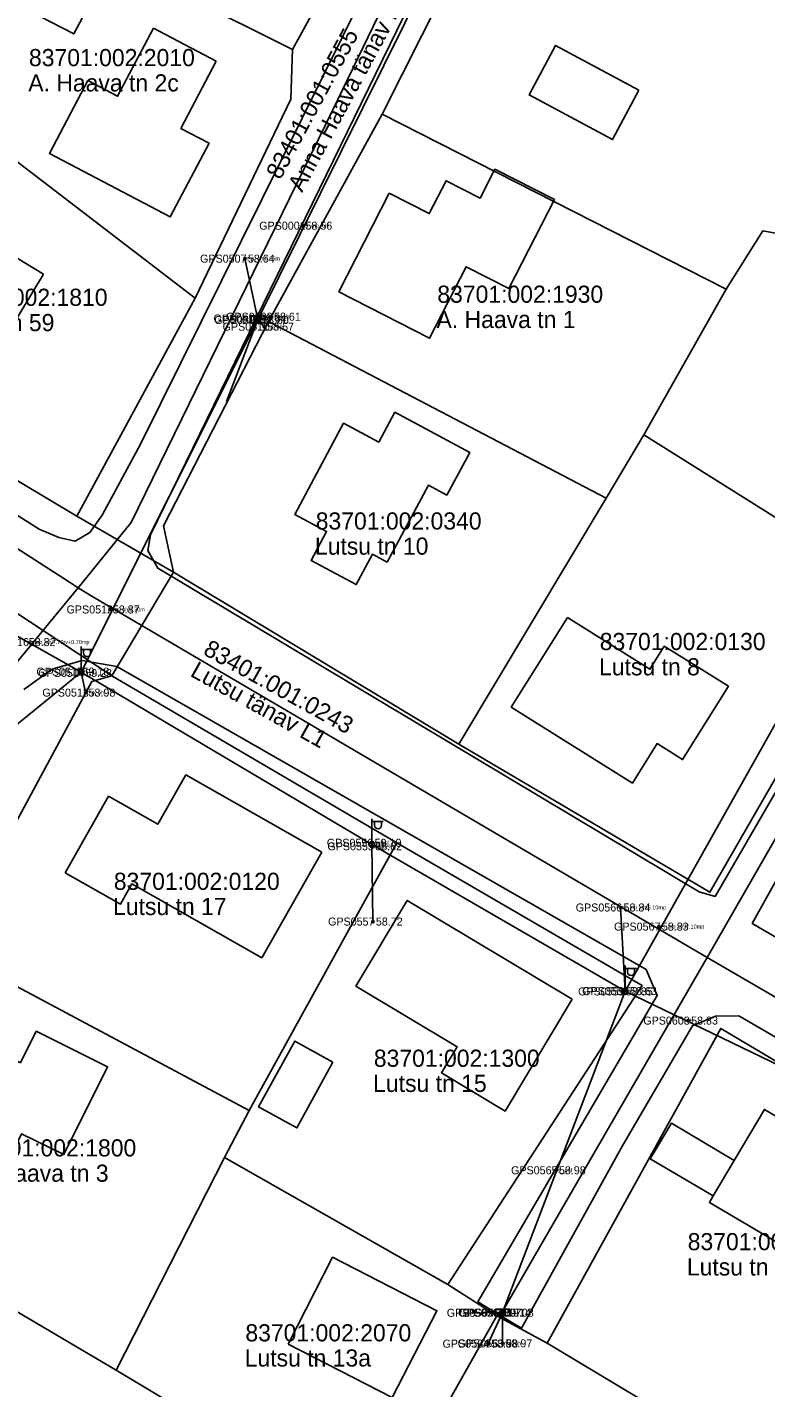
# Model space of a CAD drawing. Extents: x 580119 to 583377, y 6518915 to 6520820.
# Drawn here: x 581946.3 to 582010.9, y 6520218 to 6520337 of the extents above; entities that cross this region are included whole.
import ezdxf

# ---------------------------------------------------------------- set-up
doc = ezdxf.new("R2010")
doc.units = 0
for name, color, linetype in [('ELRAJATISMP', 7, 'Continuous'), ('Hoone Elu- või ühiskondlik hoone', 7, 'Continuous'), ('Hoone Kõrval- või tootmishoone', 7, 'Continuous'), ('L_AADRESS', 7, 'Continuous'), ('MAAMUDEL', 7, 'Continuous'), ('MOOTKORG-EH2000', 7, 'Continuous'), ('MOOTMPUNKT', 7, 'Continuous'), ('MOOTNR', 7, 'Continuous'), ('MPOHULIIN', 7, 'Continuous'), ('PIIR', 7, 'Continuous'), ('POST', 7, 'Continuous'), ('Rippe kõrgus', 7, 'Continuous'), ('SIOHULIIN', 7, 'Continuous'), ('Tee Liiklusala', 7, 'Continuous'), ('Tee Tänav Kruuskate', 7, 'Continuous'), ('Tee Tänav Püsikate', 7, 'Continuous'), ('TUNNUS', 7, 'Continuous')]:
    doc.layers.add(name, color=color, linetype=linetype)

msp = doc.modelspace()

# ---------------------------------------------------------------- linework, layer by layer
at = {"layer": 'ELRAJATISMP'}
for p, q in [((581966.36, 6520311.73), (581966.36, 6520311.13)), ((581966.63, 6520311.73), (581966.63, 6520311.13)), ((581987.76, 6520224.87), (581987.76, 6520224.28)), ((581988.03, 6520224.87), (581988.03, 6520224.28))]:
    msp.add_line(p, q, dxfattribs=at)
for points in [[(581965.9, 6520311.73), (581967.1, 6520311.73), (581967.1, 6520311.13), (581965.9, 6520311.13)], [(581987.3, 6520224.87), (581988.49, 6520224.87), (581988.49, 6520224.28), (581987.3, 6520224.28)]]:
    msp.add_lwpolyline(points, close=True, dxfattribs=at)
at = {"layer": 'Hoone Elu- või ühiskondlik hoone'}
for points in [[(581962.85, 6520334.01), (581959.76, 6520328.13), (581962.23, 6520326.83), (581958.83, 6520320.38), (581948.27, 6520325.94), (581951.63, 6520332.31), (581954.23, 6520330.94), (581957.38, 6520336.89)], [(581977.97, 6520322.47), (581981.48, 6520320.68), (581982.95, 6520323.55), (581985.92, 6520322.03), (581987.22, 6520324.56), (581992.42, 6520321.9), (581988.43, 6520314.12), (581984.7, 6520316.02), (581981.51, 6520309.78), (581973.56, 6520313.84)], [(581947.76, 6520315.39), (581943.15, 6520307.8), (581929.97, 6520315.78), (581934.59, 6520323.38)], [(581978.46, 6520303.3), (581985.01, 6520299.79), (581983.01, 6520296.06), (581981.4, 6520296.93), (581977.79, 6520290.2), (581976.51, 6520290.89), (581975.09, 6520288.23), (581971.15, 6520290.35), (581972.5, 6520292.87), (581969.72, 6520294.36), (581973.99, 6520302.34), (581977.06, 6520300.69)], [(581993.55, 6520285.36), (582000.76, 6520280.84), (582002.02, 6520282.85), (582007.63, 6520279.34), (582003.62, 6520272.93), (582001.39, 6520274.33), (581999.23, 6520270.88), (581988.64, 6520277.52)], [(581949.64, 6520263.03), (581953.44, 6520269.73), (581957.74, 6520267.28), (581960.19, 6520271.59), (581972.08, 6520264.83), (581966.83, 6520255.6), (581955.47, 6520262.06), (581954.47, 6520260.29)], [(581993.96, 6520251.97), (581988.1, 6520242.2), (581982.56, 6520245.53), (581983.93, 6520247.81), (581975.06, 6520253.13), (581979.55, 6520260.62)], [(581939.93, 6520249.3), (581945.73, 6520246.42), (581947.11, 6520249.18), (581953.35, 6520246.07), (581949.53, 6520238.4), (581945.84, 6520240.22), (581941.75, 6520232), (581933.39, 6520236.16)], [(582022.14, 6520235.63), (582017.33, 6520227.49), (582005.97, 6520234.21), (582006.31, 6520234.79), (582008.14, 6520237.89), (582010.77, 6520242.34)], [(581969.13, 6520221.82), (581973.03, 6520229.42), (581982.14, 6520224.74), (581978.24, 6520217.15)]]:
    msp.add_lwpolyline(points, close=True, dxfattribs=at)
at = {"layer": 'Hoone Kõrval- või tootmishoone'}
for points in [[(581952.19, 6520339.77), (581950.4, 6520336.39), (581944.53, 6520339.46), (581946.33, 6520342.85)], [(581999.81, 6520331.46), (581997.5, 6520327.15), (581990.2, 6520331.05), (581992.51, 6520335.37)], [(581973.06, 6520246.48), (581969.91, 6520240.72), (581966.55, 6520242.56), (581969.71, 6520248.32)], [(582008.14, 6520237.89), (582006.31, 6520234.79), (582000.8, 6520238.03), (582002.64, 6520241.14)]]:
    msp.add_lwpolyline(points, close=True, dxfattribs=at)
at = {"layer": 'MOOTMPUNKT'}
for centre in [(581970.39, 6520319.62), (581965.36, 6520316.74), (581966.39, 6520311.5), (581966.6, 6520311.37), (581967.05, 6520310.79), (581967.64, 6520311.66), (581953.55, 6520286.06), (581950.91, 6520280.62), (581951.14, 6520280.51), (581951.43, 6520278.79), (581976.44, 6520265.66), (581976.49, 6520265.35), (581998.2, 6520260), (581976.55, 6520258.77), (582001.55, 6520258.33), (581998.41, 6520252.66), (581998.77, 6520252.69), (582004.11, 6520250.11), (581992.55, 6520237.02), (581986.93, 6520224.56), (581987.77, 6520224.57), (581988.01, 6520224.57), (581986.63, 6520221.86), (581987.88, 6520221.89)]:
    msp.add_circle(centre, 0.1, dxfattribs=at)
at = {"layer": 'MPOHULIIN'}
for p, q in [((581966.5, 6520311.43), (581965.36, 6520316.74)), ((581966.5, 6520311.43), (581967.64, 6520311.66)), ((581966.5, 6520311.43), (581967.05, 6520310.79)), ((581998.59, 6520252.67), (582017.03, 6520285.52)), ((581951.03, 6520280.57), (581951.43, 6520278.79)), ((581976.46, 6520265.51), (581976.55, 6520258.77)), ((581998.59, 6520252.67), (581998.2, 6520260)), ((581987.89, 6520224.57), (581998.59, 6520252.67)), ((581987.89, 6520224.57), (581985.24, 6520224.54)), ((581987.89, 6520224.57), (581987.88, 6520221.89))]:
    msp.add_line(p, q, dxfattribs=at)
for points in [[(581951.03, 6520280.57), (581966.5, 6520311.43), (581981.19, 6520341.05)], [(581951.03, 6520280.57), (581930.23, 6520292.3), (581906.16, 6520306.38), (581867.76, 6520298.22)], [(581951.03, 6520280.57), (581930.01, 6520263.47), (581928.35, 6520263.55)], [(581998.59, 6520252.67), (581976.46, 6520265.51), (581951.03, 6520280.57)], [(582047.56, 6520226.26), (582023.23, 6520240.78), (581998.59, 6520252.67)]]:
    msp.add_lwpolyline(points, dxfattribs=at)
at = {"layer": 'PIIR'}
for points in [[(581957.49, 6520399.79), (581993.27, 6520378.24), (581969.51, 6520335.03), (581932.94, 6520353.26)], [(581993.27, 6520378.24), (581999.92, 6520374.14), (581977.35, 6520329.37), (581967.43, 6520311.25), (581958.23, 6520293.37), (581959.11, 6520289.32), (581950.66, 6520294.21), (581961, 6520313.29), (581969.36, 6520330.69), (581969.51, 6520335.03)], [(581999.92, 6520374.14), (582031.69, 6520354.73), (582013.33, 6520318.68), (582010.64, 6520319.17), (582007.43, 6520314.06), (581977.35, 6520329.37)], [(581921.06, 6520341.05), (581927.81, 6520351.97), (581931.31, 6520350.19), (581932.94, 6520353.26), (581969.51, 6520335.03), (581969.36, 6520330.69), (581961, 6520313.29), (581938.63, 6520330.42)], [(581938.63, 6520330.42), (581961, 6520313.29), (581950.66, 6520294.21), (581925.71, 6520309.1), (581929.71, 6520315.83), (581934.75, 6520324.34)], [(581977.35, 6520329.37), (582007.43, 6520314.06), (582000.23, 6520301.33), (581996.95, 6520295.8), (581967.43, 6520311.25)], [(582007.43, 6520314.06), (582010.64, 6520319.17), (582013.33, 6520318.68), (582033.73, 6520305.82), (582023.34, 6520287.11), (582019.09, 6520289.51), (582000.23, 6520301.33)], [(581958.23, 6520293.37), (581967.43, 6520311.25), (581996.95, 6520295.8), (581984.07, 6520274.27), (581959.11, 6520289.32)], [(581996.95, 6520295.8), (582000.23, 6520301.33), (582019.09, 6520289.51), (582014.72, 6520280.72), (582016.49, 6520279.57), (582006.01, 6520261.34), (581984.07, 6520274.27)], [(581910.68, 6520201.36), (581900.21, 6520207.51), (581917.83, 6520241.2), (581929.38, 6520263.33), (581942.22, 6520287.85), (581953.73, 6520280.26), (581951.99, 6520279.75), (581939.33, 6520256.33), (581928.04, 6520234.91)], [(581951.99, 6520279.75), (581953.73, 6520280.26), (581978.64, 6520265.66), (581965.72, 6520242.24), (581939.33, 6520256.33)], [(581965.72, 6520242.24), (581978.64, 6520265.66), (582000.08, 6520253.19), (581983.1, 6520227.03), (581963.58, 6520238.14)], [(581939.33, 6520256.33), (581965.72, 6520242.24), (581963.58, 6520238.14), (581954.1, 6520219.54), (581928.04, 6520234.91)], [(582006.96, 6520249.43), (582026.75, 6520237.66), (582010.72, 6520210.54), (581991.78, 6520221.9)], [(581928.04, 6520234.91), (581954.1, 6520219.54), (581960.82, 6520215.52), (581942.75, 6520182.07), (581910.68, 6520201.36)], [(581987.39, 6520224.3), (581991.78, 6520221.9), (582010.72, 6520210.54), (581999.63, 6520191.97), (581992.7, 6520196.04), (581976.76, 6520205.4)]]:
    msp.add_lwpolyline(points, close=True, dxfattribs=at)
for points in [[(581925.71, 6520309.1), (581950.66, 6520294.21), (581959.11, 6520289.32), (581953.73, 6520280.26), (581942.22, 6520287.85)], [(582026.75, 6520237.66), (582006.96, 6520249.43), (581991.78, 6520221.9), (581987.39, 6520224.3), (581983.1, 6520227.03), (582000.08, 6520253.19), (581978.64, 6520265.66), (581953.73, 6520280.26), (581959.11, 6520289.32), (581984.07, 6520274.27), (582006.01, 6520261.34), (582016.49, 6520279.57)]]:
    msp.add_lwpolyline(points, dxfattribs=at)
at = {"layer": 'POST'}
for p, q in [((581951.03, 6520280.82), (581951.03, 6520282.82)), ((581951.03, 6520282.57), (581952.03, 6520282.57)), ((581951.25, 6520282.24), (581951.25, 6520282.57)), ((581951.87, 6520282.24), (581951.87, 6520282.57)), ((581951.03, 6520280.57), (581951.03, 6520280.57)), ((581976.46, 6520265.76), (581976.46, 6520267.76)), ((581976.46, 6520267.51), (581977.46, 6520267.51)), ((581976.69, 6520267.19), (581976.69, 6520267.51)), ((581977.3, 6520267.19), (581977.3, 6520267.51)), ((581976.46, 6520265.51), (581976.46, 6520265.51)), ((581998.59, 6520252.92), (581998.59, 6520254.92)), ((581998.59, 6520254.67), (581999.59, 6520254.67)), ((581998.82, 6520254.35), (581998.82, 6520254.67)), ((581999.43, 6520254.35), (581999.43, 6520254.67)), ((581998.59, 6520252.67), (581998.59, 6520252.67))]:
    msp.add_line(p, q, dxfattribs=at)
msp.add_lwpolyline([(581986.63, 6520221.86), (581987.89, 6520224.57)], dxfattribs=at)
for centre, radius in [((581966.5, 6520311.43), 0.25), ((581951.03, 6520280.57), 0.25), ((581976.46, 6520265.51), 0.25), ((581998.59, 6520252.67), 0.25), ((581987.89, 6520224.57), 0.25), ((581986.63, 6520221.86), 0.125), ((581986.63, 6520221.86), 0.105), ((581986.63, 6520221.86), 0.0851), ((581986.63, 6520221.86), 0.0651), ((581986.63, 6520221.86), 0.0451), ((581986.63, 6520221.86), 0.0251), ((581986.63, 6520221.86), 0.00511)]:
    msp.add_circle(centre, radius, dxfattribs=at)
for centre in [(581951.56, 6520282.24), (581977, 6520267.19), (581999.12, 6520254.35)]:
    msp.add_arc(centre, 0.306, 180, 0, dxfattribs=at)
at = {"layer": 'SIOHULIIN'}
msp.add_line((581966.5, 6520311.43), (581963.76, 6520304.26), dxfattribs=at)
msp.add_lwpolyline([(581966.5, 6520311.43), (581981.19, 6520341.05), (581994.37, 6520374.96)], dxfattribs=at)
at = {"layer": 'Tee Liiklusala'}
for points in [[(581921.78, 6520309.33), (581947.38, 6520293.09), (581949.09, 6520292.34), (581950.51, 6520292.03), (581951.8, 6520292.79), (581952.88, 6520294.31), (581956.24, 6520300.51), (581975.67, 6520339.74), (581994.38, 6520376.25), (581993.59, 6520378.48), (581990.83, 6520381), (581970.52, 6520393.78), (581944.66, 6520409.33)], [(581979.24, 6520337.95), (581957.1, 6520292.6), (581956.88, 6520291.23), (581957.74, 6520289.67), (582005.07, 6520261.36), (582006.47, 6520260.97), (582013.92, 6520273.85)], [(582033.96, 6520197.24), (582049.88, 6520224.64), (582049.78, 6520225.96), (582049.2, 6520226.89), (582008.55, 6520250.53), (582006.49, 6520250.5), (582004.48, 6520249.64), (581998.41, 6520239.21), (581989.53, 6520223.21), (581987.68, 6520224.32), (581985.73, 6520225.53), (582001.41, 6520252.29), (582000.45, 6520254.57), (581954.17, 6520281.06), (581951.12, 6520281.6), (581948.5, 6520280.84), (581946.04, 6520279.06)], [(582020.85, 6520278.61), (582009.71, 6520258.61), (582031.64, 6520245.86)]]:
    msp.add_lwpolyline(points, dxfattribs=at)
at = {"layer": 'Tee Tänav Kruuskate'}
for points in [[(582005.78, 6520255.62), (582015.68, 6520272.89), (582023.19, 6520287.15)], [(582005.78, 6520255.62), (581987.68, 6520224.32)]]:
    msp.add_lwpolyline(points, dxfattribs=at)
at = {"layer": 'Tee Tänav Püsikate'}
for points in [[(581950.77, 6520287.95), (581955.41, 6520293.68), (581973.04, 6520329.74), (581977.45, 6520338.84), (581983.45, 6520350.53), (582000.38, 6520383.48)], [(581905.59, 6520312.25), (581910.07, 6520311.41), (581914.98, 6520309.92), (581920.58, 6520307.14), (581927.05, 6520303.19), (581949.43, 6520288.83), (581950.77, 6520287.95)], [(581904.38, 6520197.95), (581905.85, 6520205.86), (581916.75, 6520226.48), (581928.74, 6520250.02), (581944.37, 6520280.16), (581950.77, 6520287.95)], [(581950.77, 6520287.95), (581951.78, 6520287.33), (582005.78, 6520255.62)], [(582005.78, 6520255.62), (582053.97, 6520227.58)]]:
    msp.add_lwpolyline(points, dxfattribs=at)

# ---------------------------------------------------------------- texts
at = {"layer": 'L_AADRESS'}
for s, rotation, p in [('Anna Haava tänav L4', 61.6387, (581970.36, 6520322.47)), ('Lutsu tänav L1', 330.8609, (581960.49, 6520280.28))]:
    msp.add_text(s, height=1.5, rotation=rotation, dxfattribs=at).set_placement(p)
for s, p in [('A. Haava tn 2c', (581946.42, 6520331.36)), ('A. Haava tn 1', (581982.11, 6520310.67)), ('Lutsu tn 59', (581938.78, 6520310.4)), ('Lutsu tn 10', (581971.48, 6520290.85)), ('Lutsu tn 8', (581996.32, 6520280.3)), ('Lutsu tn 17', (581953.83, 6520259.34)), ('Lutsu tn 15', (581976.57, 6520243.87)), ('A. Haava tn 3', (581941.29, 6520236.02)), ('Lutsu tn 11', (582004, 6520227.82)), ('Lutsu tn 13a', (581965.34, 6520219.86))]:
    msp.add_text(s, height=1.5, dxfattribs=at).set_placement(p)
at = {"layer": 'MAAMUDEL'}
for s, p in [(' el_mp_ohl', (581970.39, 6520319.45)), (' mp_ohl6.55m', (581965.36, 6520316.57)), (' mp_ohl', (581967.05, 6520310.62)), (' mp_ohl', (581967.64, 6520311.49)), (' mp_ohl6.70m', (581953.55, 6520285.88)), (' mp_ohl', (581951.43, 6520278.62)), (' kaabel', (581976.44, 6520265.49)), (' kaabel', (581976.49, 6520265.17)), (' tv', (582004.11, 6520249.94)), (' si_ohl', (581992.55, 6520236.84)), (' mp_ohl', (581986.93, 6520224.39)), (' mp_ohl', (581987.88, 6520221.72))]:
    msp.add_text(s, height=0.35, dxfattribs=at).set_placement(p)
at = {"layer": 'MOOTKORG-EH2000'}
for s, p in [(' 58.56', (581970.39, 6520319.27)), (' 58.64', (581965.36, 6520316.39)), (' 58.61', (581967.64, 6520311.31)), (' 58.64', (581966.39, 6520311.15)), (' 58.60', (581966.6, 6520311.02)), (' 58.57', (581967.05, 6520310.44)), (' 58.87', (581953.55, 6520285.71)), (' 58.82', (581946.2, 6520282.86)), (' 59.18', (581950.91, 6520280.27)), (' 59.23', (581951.14, 6520280.16)), (' 58.98', (581951.43, 6520278.44)), (' 59.10', (581976.44, 6520265.31)), (' 58.62', (581976.49, 6520265)), (' 58.84', (581998.2, 6520259.65)), (' 58.72', (581976.55, 6520258.42)), (' 58.83', (582001.55, 6520257.98)), (' 58.85', (581998.41, 6520252.31)), (' 58.63', (581998.77, 6520252.34)), (' 58.83', (582004.11, 6520249.76)), (' 58.98', (581992.55, 6520236.67)), (' 59.07', (581986.93, 6520224.21)), (' 59.14', (581987.77, 6520224.22)), (' 59.08', (581988.01, 6520224.22)), (' 58.98', (581986.63, 6520221.51)), (' 58.97', (581987.88, 6520221.54))]:
    msp.add_text(s, height=0.7, dxfattribs=at).set_placement(p)
at = {"layer": 'MOOTNR'}
for s, p in [('GPS0001 ', (581966.61, 6520319.27)), ('GPS0507 ', (581961.44, 6520316.39)), ('GPS0508 ', (581963.72, 6520311.31)), ('GPS0510 ', (581962.61, 6520311.15)), ('GPS0509 ', (581962.68, 6520311.02)), ('GPS0511 ', (581963.41, 6520310.44)), ('GPS0512 ', (581949.77, 6520285.71)), ('GPS0516 ', (581942.42, 6520282.86)), ('GPS0515 ', (581947.13, 6520280.27)), ('GPS0514 ', (581947.29, 6520280.16)), ('GPS0513 ', (581947.65, 6520278.44)), ('GPS0556 ', (581972.52, 6520265.31)), ('GPS0555 ', (581972.57, 6520265)), ('GPS0566 ', (581994.28, 6520259.65)), ('GPS0557 ', (581972.63, 6520258.42)), ('GPS0567 ', (581997.63, 6520257.98)), ('GPS0559 ', (581994.49, 6520252.31)), ('GPS0558 ', (581994.85, 6520252.34)), ('GPS0608 ', (582000.19, 6520249.76)), ('GPS0565 ', (581988.63, 6520236.67)), ('GPS0562 ', (581983.01, 6520224.21)), ('GPS0561 ', (581984, 6520224.22)), ('GPS0560 ', (581984.09, 6520224.22)), ('GPS0564 ', (581982.64, 6520221.51)), ('GPS0563 ', (581983.96, 6520221.54))]:
    msp.add_text(s, height=0.7, dxfattribs=at).set_placement(p)
at = {"layer": 'Rippe kõrgus'}
for s, p in [(' el_mp_ohl7.70tv+0.70mp', (581946.2, 6520283.04)), (' el_mp_ohl6.10mp', (581998.2, 6520259.83)), (' el_mp_ohl7.10mp', (582001.55, 6520258.16))]:
    msp.add_text(s, height=0.35, dxfattribs=at).set_placement(p)
at = {"layer": 'TUNNUS'}
for s, rotation, p in [('83401:001:0555', 61.6387, (581968.45, 6520323.57)), ('83401:001:0243', 330.8609, (581961.62, 6520282.18))]:
    msp.add_text(s, height=1.5, rotation=rotation, dxfattribs=at).set_placement(p)
for s, p in [('83701:002:2010', (581946.48, 6520333.57)), ('83701:002:1930', (581982.18, 6520312.88)), ('83701:002:1810', (581938.85, 6520312.61)), ('83701:002:0340', (581971.55, 6520293.05)), ('83701:002:0130', (581996.38, 6520282.51)), ('83701:002:0120', (581953.9, 6520261.54)), ('83701:002:1300', (581976.63, 6520246.07)), ('83701:002:1800', (581941.36, 6520238.23)), ('83701:002:2080', (582004.07, 6520230.03)), ('83701:002:2070', (581965.4, 6520222.06))]:
    msp.add_text(s, height=1.5, dxfattribs=at).set_placement(p)

doc.saveas('drawing.dxf')
